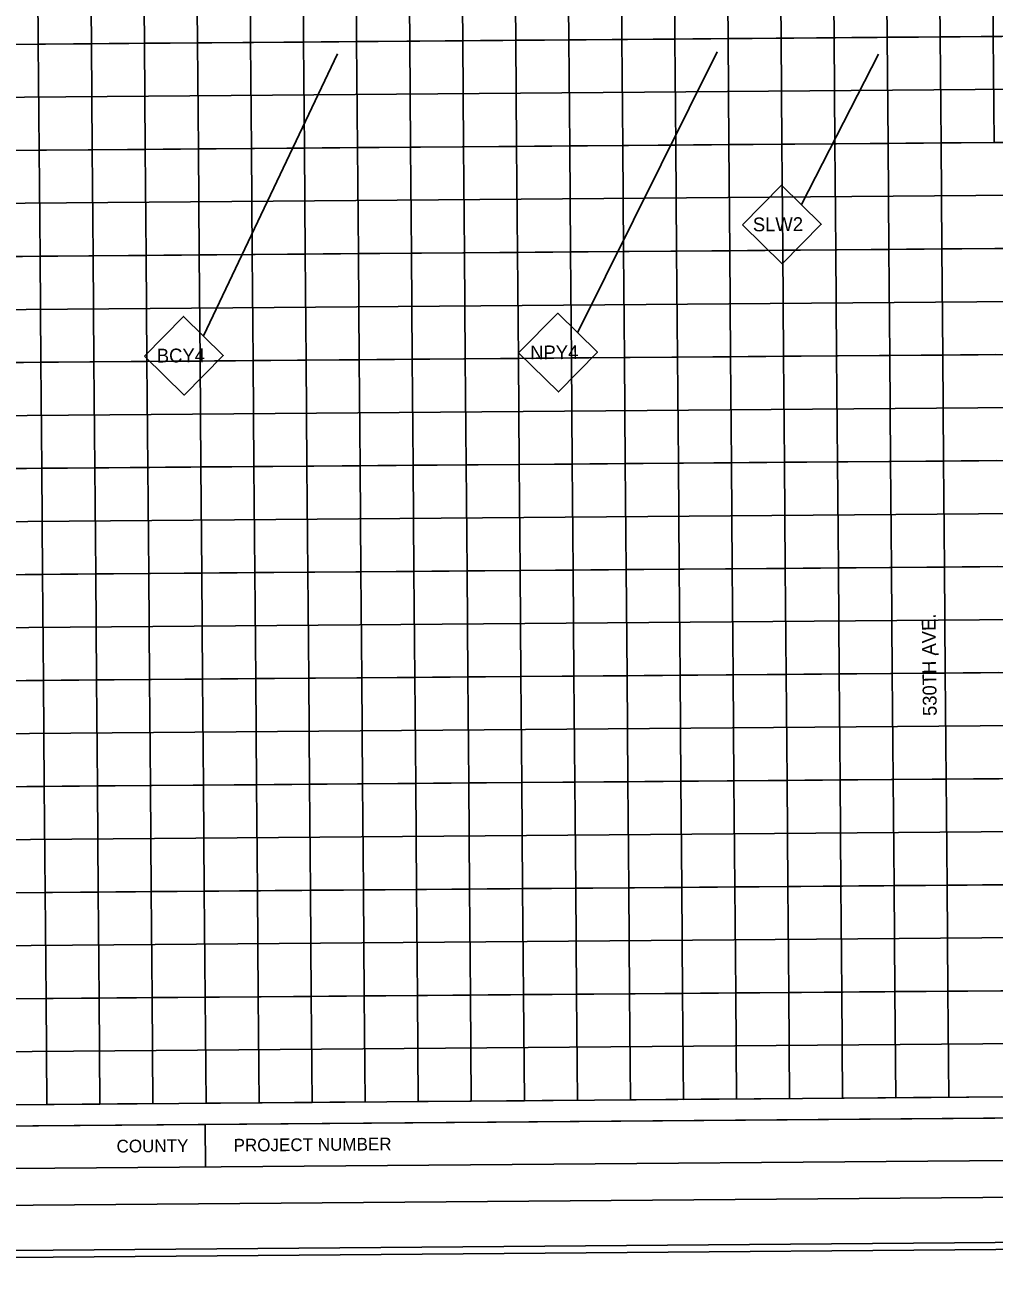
# Model space of a CAD drawing. Extents: x 11670159 to 11702568, y 9558247 to 9571922.
# Drawn here: x 11687520 to 11689347, y 9566402 to 9568756 of the extents above; entities that cross this region are included whole.
import ezdxf

# ---------------------------------------------------------------- set-up
doc = ezdxf.new("R2010")
doc.units = 0
for name, color, linetype in [('dsnNonPlotable', 7, 'Continuous'), ('DsnShtHorizMidLine', 7, 'Continuous'), ('DsnShtInsideBorder', 7, 'Continuous'), ('DsnShtMajorGrid01', 7, 'Continuous'), ('DsnShtMajorGrid02', 7, 'Continuous'), ('DsnShtMajorGrid03', 7, 'Continuous'), ('DsnShtMajorGrid04', 7, 'Continuous'), ('DsnShtMajorGrid05', 7, 'Continuous'), ('DsnShtMajorGrid06', 7, 'Continuous'), ('DsnShtMajorGrid07', 7, 'Continuous'), ('DsnShtMajorGrid08', 7, 'Continuous'), ('DsnShtMajorGrid09', 7, 'Continuous'), ('DsnShtMajorGrid10', 7, 'Continuous'), ('DsnShtMajorGrid11', 7, 'Continuous'), ('DsnShtMinorGrid01', 7, 'Continuous'), ('DsnShtMinorGrid02', 7, 'Continuous'), ('DsnShtMinorGrid03', 7, 'Continuous'), ('DsnShtMinorGrid04', 7, 'Continuous'), ('DsnShtMinorGrid05', 7, 'Continuous'), ('DsnShtMinorGrid06', 7, 'Continuous'), ('DsnShtMinorGrid07', 7, 'Continuous'), ('DsnShtMinorGrid08', 7, 'Continuous'), ('DsnShtMinorGrid09', 7, 'Continuous'), ('DsnShtMinorGrid10', 7, 'Continuous'), ('DsnShtMinorGrid11', 7, 'Continuous'), ('DsnShtOutsideBorder', 7, 'Continuous'), ('DsnShtPlotShape', 7, 'Continuous'), ('dsnShtPlotShapeBatchPrint', 7, 'Continuous'), ('dsnTextFinalPlan', 7, 'Continuous'), ('hwyPlanSheetShape', 7, 'Continuous'), ('PvmtMrkngPrplCallout', 7, 'Continuous')]:
    doc.layers.add(name, color=color, linetype=linetype)

msp = doc.modelspace()

# ---------------------------------------------------------------- linework, layer by layer
at = {"layer": 'dsnNonPlotable'}
msp.add_line((11689237.5, 9567569), (11689242.3, 9567569.1), dxfattribs=at)
msp.add_lwpolyline([(11684229.4, 9570693), (11690229.2, 9570741.4), (11690261.8, 9566701.6), (11684262, 9566653.2)], close=True, dxfattribs=at)
at = {"layer": 'DsnShtHorizMidLine'}
msp.add_line((11684110.5, 9568692), (11690380.3, 9568742.6), dxfattribs=at)
at = {"layer": 'DsnShtInsideBorder'}
msp.add_line((11687859.9, 9566682.2), (11687860.5, 9566602.2), dxfattribs=at)
at = {"layer": 'DsnShtMajorGrid01'}
for points in [[(11690394.8, 9566942.6), (11684125, 9566892.1)], [(11687461.5, 9566719), (11687661.5, 9566720.6), (11687659.9, 9566920.6), (11687859.9, 9566922.2), (11687861.5, 9566722.2), (11688061.5, 9566723.8), (11688059.9, 9566923.8), (11688259.9, 9566925.4), (11688261.5, 9566725.4), (11688461.5, 9566727), (11688459.9, 9566927), (11688659.9, 9566928.6), (11688661.5, 9566728.6), (11688861.5, 9566730.3), (11688859.9, 9566930.3), (11689059.9, 9566931.9), (11689061.5, 9566731.9), (11689261.5, 9566733.5), (11689259.9, 9566933.5), (11689459.9, 9566935.1)], [(11690396.5, 9566742.6), (11684126.7, 9566692.1)]]:
    msp.add_lwpolyline(points, dxfattribs=at)
at = {"layer": 'DsnShtMajorGrid02'}
for points in [[(11690393.2, 9567142.6), (11684123.4, 9567092.1)], [(11687459.9, 9566919), (11687659.9, 9566920.6), (11687658.3, 9567120.6), (11687858.3, 9567122.2), (11687859.9, 9566922.2), (11688059.9, 9566923.8), (11688058.3, 9567123.8), (11688258.3, 9567125.4), (11688259.9, 9566925.4), (11688459.9, 9566927), (11688458.3, 9567127), (11688658.3, 9567128.6), (11688659.9, 9566928.6), (11688859.9, 9566930.3), (11688858.3, 9567130.2), (11689058.3, 9567131.9), (11689059.9, 9566931.9), (11689259.9, 9566933.5), (11689258.3, 9567133.5), (11689458.3, 9567135.1)], [(11690394.8, 9566942.6), (11684125, 9566892.1)]]:
    msp.add_lwpolyline(points, dxfattribs=at)
at = {"layer": 'DsnShtMajorGrid03'}
for points in [[(11690391.6, 9567342.6), (11684121.8, 9567292)], [(11687458.3, 9567119), (11687658.3, 9567120.6), (11687656.7, 9567320.6), (11687856.7, 9567322.2), (11687858.3, 9567122.2), (11688058.3, 9567123.8), (11688056.7, 9567323.8), (11688256.7, 9567325.4), (11688258.3, 9567125.4), (11688458.3, 9567127), (11688456.7, 9567327), (11688656.7, 9567328.6), (11688658.3, 9567128.6), (11688858.3, 9567130.2), (11688856.7, 9567330.2), (11689056.7, 9567331.9), (11689058.3, 9567131.9), (11689258.3, 9567133.5), (11689256.6, 9567333.5), (11689456.6, 9567335.1)], [(11690393.2, 9567142.6), (11684123.4, 9567092.1)]]:
    msp.add_lwpolyline(points, dxfattribs=at)
at = {"layer": 'DsnShtMajorGrid04'}
for points in [[(11690390, 9567542.6), (11684120.2, 9567492)], [(11687456.7, 9567318.9), (11687656.7, 9567320.6), (11687655.1, 9567520.6), (11687855.1, 9567522.2), (11687856.7, 9567322.2), (11688056.7, 9567323.8), (11688055.1, 9567523.8), (11688255.1, 9567525.4), (11688256.7, 9567325.4), (11688456.7, 9567327), (11688455.1, 9567527), (11688655.1, 9567528.6), (11688656.7, 9567328.6), (11688856.7, 9567330.2), (11688855, 9567530.2), (11689055, 9567531.8), (11689056.7, 9567331.9), (11689256.6, 9567333.5), (11689255, 9567533.5), (11689455, 9567535.1)], [(11690391.6, 9567342.6), (11684121.8, 9567292)]]:
    msp.add_lwpolyline(points, dxfattribs=at)
at = {"layer": 'DsnShtMajorGrid05'}
for points in [[(11690388.4, 9567742.6), (11684118.6, 9567692)], [(11687455.1, 9567518.9), (11687655.1, 9567520.6), (11687653.5, 9567720.5), (11687853.5, 9567722.2), (11687855.1, 9567522.2), (11688055.1, 9567523.8), (11688053.5, 9567723.8), (11688253.5, 9567725.4), (11688255.1, 9567525.4), (11688455.1, 9567527), (11688453.4, 9567727), (11688653.4, 9567728.6), (11688655.1, 9567528.6), (11688855, 9567530.2), (11688853.4, 9567730.2), (11689053.4, 9567731.8), (11689055, 9567531.8), (11689255, 9567533.5), (11689253.4, 9567733.5), (11689453.4, 9567735.1)], [(11690390, 9567542.6), (11684120.2, 9567492)]]:
    msp.add_lwpolyline(points, dxfattribs=at)
at = {"layer": 'DsnShtMajorGrid06'}
for points in [[(11690386.8, 9567942.6), (11684117, 9567892)], [(11687453.5, 9567718.9), (11687653.5, 9567720.5), (11687651.9, 9567920.5), (11687851.9, 9567922.2), (11687853.5, 9567722.2), (11688053.5, 9567723.8), (11688051.8, 9567923.8), (11688251.8, 9567925.4), (11688253.5, 9567725.4), (11688453.4, 9567727), (11688451.8, 9567927), (11688651.8, 9567928.6), (11688653.4, 9567728.6), (11688853.4, 9567730.2), (11688851.8, 9567930.2), (11689051.8, 9567931.8), (11689053.4, 9567731.8), (11689253.4, 9567733.5), (11689251.8, 9567933.4), (11689451.8, 9567935.1)], [(11690388.4, 9567742.6), (11684118.6, 9567692)]]:
    msp.add_lwpolyline(points, dxfattribs=at)
at = {"layer": 'DsnShtMajorGrid07'}
for points in [[(11690385.2, 9568142.6), (11684115.4, 9568092)], [(11687451.9, 9567918.9), (11687651.9, 9567920.5), (11687650.2, 9568120.5), (11687850.2, 9568122.1), (11687851.9, 9567922.2), (11688051.8, 9567923.8), (11688050.2, 9568123.8), (11688250.2, 9568125.4), (11688251.8, 9567925.4), (11688451.8, 9567927), (11688450.2, 9568127), (11688650.2, 9568128.6), (11688651.8, 9567928.6), (11688851.8, 9567930.2), (11688850.2, 9568130.2), (11689050.2, 9568131.8), (11689051.8, 9567931.8), (11689251.8, 9567933.4), (11689250.2, 9568133.4), (11689450.2, 9568135.1)], [(11690386.8, 9567942.6), (11684117, 9567892)]]:
    msp.add_lwpolyline(points, dxfattribs=at)
at = {"layer": 'DsnShtMajorGrid08'}
for points in [[(11690383.5, 9568342.6), (11684113.7, 9568292)], [(11687450.3, 9568118.9), (11687650.2, 9568120.5), (11687648.6, 9568320.5), (11687848.6, 9568322.1), (11687850.2, 9568122.1), (11688050.2, 9568123.8), (11688048.6, 9568323.8), (11688248.6, 9568325.4), (11688250.2, 9568125.4), (11688450.2, 9568127), (11688448.6, 9568327), (11688648.6, 9568328.6), (11688650.2, 9568128.6), (11688850.2, 9568130.2), (11688848.6, 9568330.2), (11689048.6, 9568331.8), (11689050.2, 9568131.8), (11689250.2, 9568133.4), (11689248.6, 9568333.4), (11689448.6, 9568335)], [(11690385.2, 9568142.6), (11684115.4, 9568092)]]:
    msp.add_lwpolyline(points, dxfattribs=at)
at = {"layer": 'DsnShtMajorGrid09'}
for points in [[(11690381.9, 9568542.6), (11684112.1, 9568492)], [(11687448.6, 9568318.9), (11687648.6, 9568320.5), (11687647, 9568520.5), (11687847, 9568522.1), (11687848.6, 9568322.1), (11688048.6, 9568323.8), (11688047, 9568523.7), (11688247, 9568525.4), (11688248.6, 9568325.4), (11688448.6, 9568327), (11688447, 9568527), (11688647, 9568528.6), (11688648.6, 9568328.6), (11688848.6, 9568330.2), (11688847, 9568530.2), (11689047, 9568531.8), (11689048.6, 9568331.8), (11689248.6, 9568333.4), (11689247, 9568533.4), (11689447, 9568535)], [(11690383.5, 9568342.6), (11684113.7, 9568292)]]:
    msp.add_lwpolyline(points, dxfattribs=at)
at = {"layer": 'DsnShtMajorGrid10'}
for points in [[(11690380.3, 9568742.6), (11684110.5, 9568692)], [(11687447, 9568518.9), (11687647, 9568520.5), (11687645.4, 9568720.5), (11687845.4, 9568722.1), (11687847, 9568522.1), (11688047, 9568523.7), (11688045.4, 9568723.7), (11688245.4, 9568725.4), (11688247, 9568525.4), (11688447, 9568527), (11688445.4, 9568727), (11688645.4, 9568728.6), (11688647, 9568528.6), (11688847, 9568530.2), (11688845.4, 9568730.2), (11689045.4, 9568731.8), (11689047, 9568531.8), (11689247, 9568533.4), (11689245.4, 9568733.4), (11689445.3, 9568735)], [(11690381.9, 9568542.6), (11684112.1, 9568492)]]:
    msp.add_lwpolyline(points, dxfattribs=at)
at = {"layer": 'DsnShtMajorGrid11'}
for points in [[(11690243.7, 9568941.5), (11690245.3, 9568741.5), (11690380.3, 9568742.6), (11684110.5, 9568692)], [(11687445.4, 9568718.9), (11687645.4, 9568720.5), (11687643.8, 9568920.5)], [(11687843.8, 9568922.1), (11687845.4, 9568722.1), (11688045.4, 9568723.7), (11688043.8, 9568923.7)], [(11688243.8, 9568925.3), (11688245.4, 9568725.4), (11688445.4, 9568727), (11688443.8, 9568927)], [(11688643.8, 9568928.6), (11688645.4, 9568728.6), (11688845.4, 9568730.2), (11688843.8, 9568930.2)], [(11689043.7, 9568931.8), (11689045.4, 9568731.8), (11689245.4, 9568733.4), (11689243.7, 9568933.4)]]:
    msp.add_lwpolyline(points, dxfattribs=at)
at = {"layer": 'DsnShtMinorGrid01'}
for points in [[(11687359.9, 9566918.2), (11687559.9, 9566919.8), (11687561.5, 9566719.8), (11687761.5, 9566721.4), (11687759.9, 9566921.4), (11687959.9, 9566923), (11687961.5, 9566723), (11688161.5, 9566724.6), (11688159.9, 9566924.6), (11688359.9, 9566926.2), (11688361.5, 9566726.2), (11688561.5, 9566727.8), (11688559.9, 9566927.8), (11688759.9, 9566929.4), (11688761.5, 9566729.5), (11688961.5, 9566731.1), (11688959.9, 9566931.1), (11689159.9, 9566932.7), (11689161.5, 9566732.7), (11689361.5, 9566734.3)], [(11690260.6, 9566841.5), (11684260.8, 9566793.1)]]:
    msp.add_lwpolyline(points, dxfattribs=at)
at = {"layer": 'DsnShtMinorGrid02'}
for points in [[(11687358.3, 9567118.1), (11687558.3, 9567119.8), (11687559.9, 9566919.8), (11687759.9, 9566921.4), (11687758.3, 9567121.4), (11687958.3, 9567123), (11687959.9, 9566923), (11688159.9, 9566924.6), (11688158.3, 9567124.6), (11688358.3, 9567126.2), (11688359.9, 9566926.2), (11688559.9, 9566927.8), (11688558.3, 9567127.8), (11688758.3, 9567129.4), (11688759.9, 9566929.4), (11688959.9, 9566931.1), (11688958.3, 9567131.1), (11689158.3, 9567132.7), (11689159.9, 9566932.7), (11689359.9, 9566934.3)], [(11690259, 9567041.5), (11684259.2, 9566993.1)]]:
    msp.add_lwpolyline(points, dxfattribs=at)
at = {"layer": 'DsnShtMinorGrid03'}
for points in [[(11687356.7, 9567318.1), (11687556.7, 9567319.8), (11687558.3, 9567119.8), (11687758.3, 9567121.4), (11687756.7, 9567321.4), (11687956.7, 9567323), (11687958.3, 9567123), (11688158.3, 9567124.6), (11688156.7, 9567324.6), (11688356.7, 9567326.2), (11688358.3, 9567126.2), (11688558.3, 9567127.8), (11688556.7, 9567327.8), (11688756.7, 9567329.4), (11688758.3, 9567129.4), (11688958.3, 9567131.1), (11688956.7, 9567331), (11689156.7, 9567332.7), (11689158.3, 9567132.7), (11689358.3, 9567134.3)], [(11690257.4, 9567241.5), (11684257.6, 9567193.1)]]:
    msp.add_lwpolyline(points, dxfattribs=at)
at = {"layer": 'DsnShtMinorGrid04'}
for points in [[(11687355.1, 9567518.1), (11687555.1, 9567519.7), (11687556.7, 9567319.8), (11687756.7, 9567321.4), (11687755.1, 9567521.4), (11687955.1, 9567523), (11687956.7, 9567323), (11688156.7, 9567324.6), (11688155.1, 9567524.6), (11688355.1, 9567526.2), (11688356.7, 9567326.2), (11688556.7, 9567327.8), (11688555.1, 9567527.8), (11688755.1, 9567529.4), (11688756.7, 9567329.4), (11688956.7, 9567331), (11688955, 9567531), (11689155, 9567532.7), (11689156.7, 9567332.7), (11689356.6, 9567334.3)], [(11690255.8, 9567441.5), (11684256, 9567393.1)]]:
    msp.add_lwpolyline(points, dxfattribs=at)
at = {"layer": 'DsnShtMinorGrid05'}
for points in [[(11687353.5, 9567718.1), (11687553.5, 9567719.7), (11687555.1, 9567519.7), (11687755.1, 9567521.4), (11687753.5, 9567721.4), (11687953.5, 9567723), (11687955.1, 9567523), (11688155.1, 9567524.6), (11688153.5, 9567724.6), (11688353.5, 9567726.2), (11688355.1, 9567526.2), (11688555.1, 9567527.8), (11688553.4, 9567727.8), (11688753.4, 9567729.4), (11688755.1, 9567529.4), (11688955, 9567531), (11688953.4, 9567731), (11689153.4, 9567732.6), (11689155, 9567532.7), (11689355, 9567534.3)], [(11690254.2, 9567641.5), (11684254.4, 9567593.1)]]:
    msp.add_lwpolyline(points, dxfattribs=at)
at = {"layer": 'DsnShtMinorGrid06'}
for points in [[(11687351.9, 9567918.1), (11687551.9, 9567919.7), (11687553.5, 9567719.7), (11687753.5, 9567721.4), (11687751.9, 9567921.3), (11687951.9, 9567923), (11687953.5, 9567723), (11688153.5, 9567724.6), (11688151.8, 9567924.6), (11688351.8, 9567926.2), (11688353.5, 9567726.2), (11688553.4, 9567727.8), (11688551.8, 9567927.8), (11688751.8, 9567929.4), (11688753.4, 9567729.4), (11688953.4, 9567731), (11688951.8, 9567931), (11689151.8, 9567932.6), (11689153.4, 9567732.6), (11689353.4, 9567734.3)], [(11690252.6, 9567841.5), (11684252.8, 9567793.1)]]:
    msp.add_lwpolyline(points, dxfattribs=at)
at = {"layer": 'DsnShtMinorGrid07'}
for points in [[(11687350.3, 9568118.1), (11687550.3, 9568119.7), (11687551.9, 9567919.7), (11687751.9, 9567921.3), (11687750.2, 9568121.3), (11687950.2, 9568123), (11687951.9, 9567923), (11688151.8, 9567924.6), (11688150.2, 9568124.6), (11688350.2, 9568126.2), (11688351.8, 9567926.2), (11688551.8, 9567927.8), (11688550.2, 9568127.8), (11688750.2, 9568129.4), (11688751.8, 9567929.4), (11688951.8, 9567931), (11688950.2, 9568131), (11689150.2, 9568132.6), (11689151.8, 9567932.6), (11689351.8, 9567934.3)], [(11690251, 9568041.5), (11684251.2, 9567993.1)]]:
    msp.add_lwpolyline(points, dxfattribs=at)
at = {"layer": 'DsnShtMinorGrid08'}
for points in [[(11687348.6, 9568318.1), (11687548.6, 9568319.7), (11687550.3, 9568119.7), (11687750.2, 9568121.3), (11687748.6, 9568321.3), (11687948.6, 9568322.9), (11687950.2, 9568123), (11688150.2, 9568124.6), (11688148.6, 9568324.6), (11688348.6, 9568326.2), (11688350.2, 9568126.2), (11688550.2, 9568127.8), (11688548.6, 9568327.8), (11688748.6, 9568329.4), (11688750.2, 9568129.4), (11688950.2, 9568131), (11688948.6, 9568331), (11689148.6, 9568332.6), (11689150.2, 9568132.6), (11689350.2, 9568134.2)], [(11690249.4, 9568241.5), (11684249.6, 9568193.1)]]:
    msp.add_lwpolyline(points, dxfattribs=at)
at = {"layer": 'DsnShtMinorGrid09'}
for points in [[(11687347, 9568518.1), (11687547, 9568519.7), (11687548.6, 9568319.7), (11687748.6, 9568321.3), (11687747, 9568521.3), (11687947, 9568522.9), (11687948.6, 9568322.9), (11688148.6, 9568324.6), (11688147, 9568524.6), (11688347, 9568526.2), (11688348.6, 9568326.2), (11688548.6, 9568327.8), (11688547, 9568527.8), (11688747, 9568529.4), (11688748.6, 9568329.4), (11688948.6, 9568331), (11688947, 9568531), (11689147, 9568532.6), (11689148.6, 9568332.6), (11689348.6, 9568334.2)], [(11690247.7, 9568441.5), (11684247.9, 9568393.1)]]:
    msp.add_lwpolyline(points, dxfattribs=at)
at = {"layer": 'DsnShtMinorGrid10'}
for points in [[(11687345.4, 9568718.1), (11687545.4, 9568719.7), (11687547, 9568519.7), (11687747, 9568521.3), (11687745.4, 9568721.3), (11687945.4, 9568722.9), (11687947, 9568522.9), (11688147, 9568524.6), (11688145.4, 9568724.5), (11688345.4, 9568726.2), (11688347, 9568526.2), (11688547, 9568527.8), (11688545.4, 9568727.8), (11688745.4, 9568729.4), (11688747, 9568529.4), (11688947, 9568531), (11688945.4, 9568731), (11689145.4, 9568732.6), (11689147, 9568532.6), (11689347, 9568534.2), (11689345.4, 9568734.2), (11689545.3, 9568735.8)], [(11690246.1, 9568641.5), (11684246.3, 9568593.1)]]:
    msp.add_lwpolyline(points, dxfattribs=at)
at = {"layer": 'DsnShtMinorGrid11'}
for points in [[(11687543.8, 9568919.7), (11687545.4, 9568719.7), (11687745.4, 9568721.3), (11687743.8, 9568921.3)], [(11687943.8, 9568922.9), (11687945.4, 9568722.9), (11688145.4, 9568724.5), (11688143.8, 9568924.5)], [(11688343.8, 9568926.2), (11688345.4, 9568726.2), (11688545.4, 9568727.8), (11688543.8, 9568927.8)], [(11688743.8, 9568929.4), (11688745.4, 9568729.4), (11688945.4, 9568731), (11688943.8, 9568931)], [(11689143.7, 9568932.6), (11689145.4, 9568732.6), (11689345.4, 9568734.2), (11689343.7, 9568934.2)]]:
    msp.add_lwpolyline(points, dxfattribs=at)
at = {"layer": 'DsnShtOutsideBorder'}
for p, q in [((11684866.8, 9566658), (11687859.9, 9566682.2)), ((11687859.9, 9566682.2), (11689348.3, 9566694.2)), ((11687859.9, 9566682.2), (11687860.5, 9566602.2))]:
    msp.add_line(p, q, dxfattribs=at)
msp.add_lwpolyline([(11684094.4, 9570691.9), (11690364.2, 9570742.5), (11690397.4, 9566622.6), (11684127.6, 9566572.1)], close=True, dxfattribs=at)
at = {"layer": 'DsnShtPlotShape'}
msp.add_lwpolyline([(11683828.5, 9570801.8), (11690628.3, 9570856.6), (11690663.8, 9566456.8), (11683864, 9566401.9)], close=True, dxfattribs=at)
at = {"layer": 'dsnShtPlotShapeBatchPrint'}
msp.add_lwpolyline([(11683907.6, 9570802.4), (11690549.2, 9570856), (11690584.6, 9566469.3), (11683943, 9566415.7)], close=True, dxfattribs=at)
at = {"layer": 'hwyPlanSheetShape'}
msp.add_lwpolyline([(11683998.8, 9570760.1), (11690458.6, 9570812.2), (11690493, 9566554), (11684033.2, 9566501.9)], close=True, dxfattribs=at)
at = {"layer": 'PvmtMrkngPrplCallout'}
for p, q in [((11687856.7, 9568169.5), (11688109.4, 9568701.7)), ((11688561.8, 9568175.4), (11688824.7, 9568705.3)), ((11688983.7, 9568417), (11689129.3, 9568701.1))]:
    msp.add_line(p, q, dxfattribs=at)
for points in [[(11688872.7, 9568379), (11688946.3, 9568453.8), (11689021.2, 9568380.2), (11688947.5, 9568305.3)], [(11688450.8, 9568137.4), (11688524.4, 9568212.2), (11688599.2, 9568138.6), (11688525.6, 9568063.8)], [(11687745.6, 9568131.5), (11687819.3, 9568206.3), (11687894.1, 9568132.7), (11687820.5, 9568057.8)]]:
    msp.add_lwpolyline(points, close=True, dxfattribs=at)

# ---------------------------------------------------------------- texts
at = {"layer": 'DsnShtInsideBorder'}
for s, p in [('COUNTY', (11687692.9, 9566629.2)), ('PROJECT NUMBER', (11687913.5, 9566631))]:
    msp.add_text(s, height=24, rotation=0.4622, dxfattribs=at).set_placement(p)
at = {"layer": 'dsnTextFinalPlan'}
msp.add_text('530TH AVE.', height=26, rotation=90.7153, dxfattribs=at).set_placement((11689238.9, 9567452.7))
at = {"layer": 'PvmtMrkngPrplCallout'}
for s, p in [('SLW2', (11688892.3, 9568366.6)), ('BCY4', (11687768.8, 9568119.2)), ('NPY4', (11688472.6, 9568125.1))]:
    msp.add_text(s, height=26, rotation=0.4622, dxfattribs=at).set_placement(p)

doc.saveas('drawing.dxf')
